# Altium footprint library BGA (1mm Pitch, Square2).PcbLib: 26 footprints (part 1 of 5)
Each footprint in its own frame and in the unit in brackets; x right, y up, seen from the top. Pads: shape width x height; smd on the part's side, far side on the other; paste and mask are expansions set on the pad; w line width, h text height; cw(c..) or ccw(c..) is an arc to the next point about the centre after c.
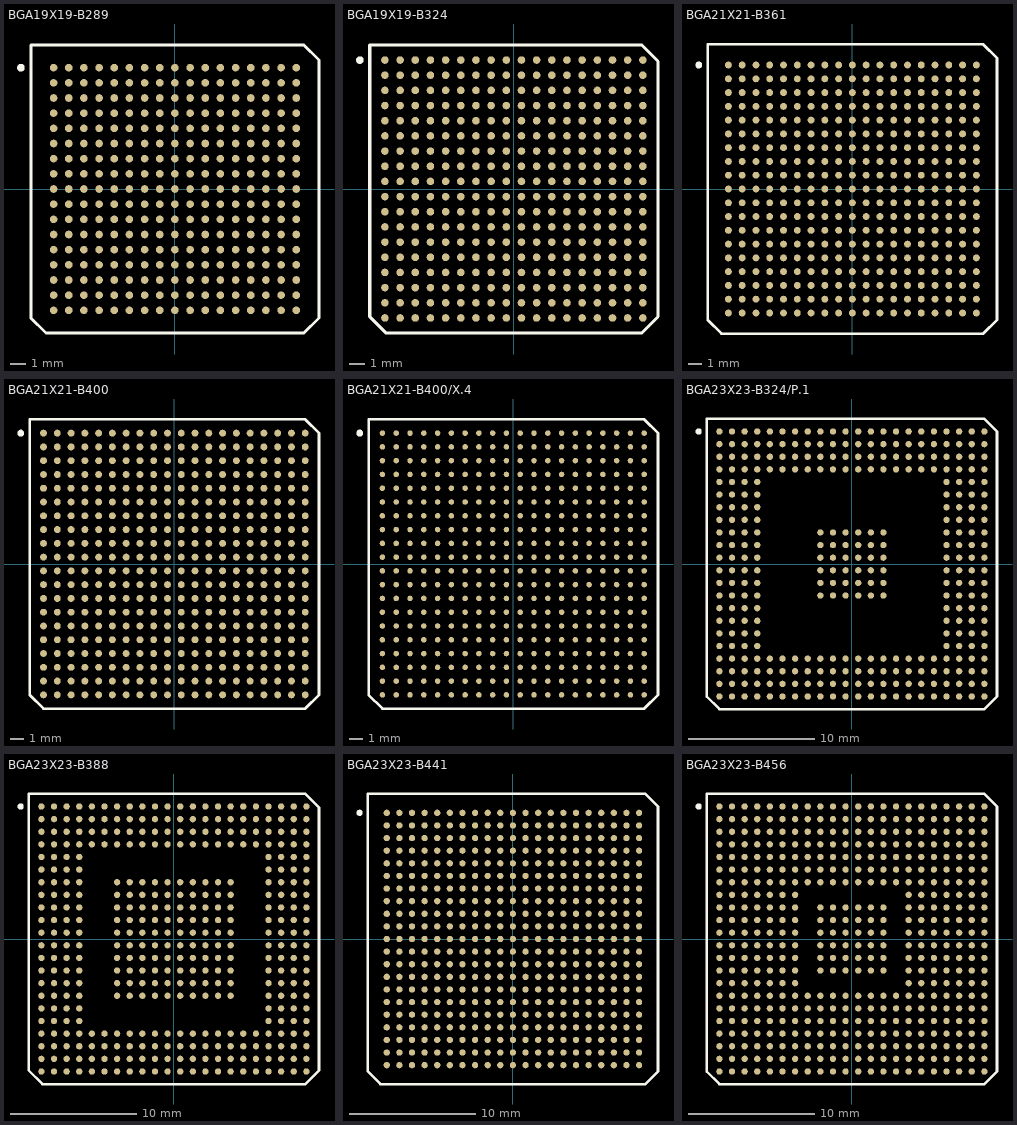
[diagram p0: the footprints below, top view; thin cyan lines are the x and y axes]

## BGA19X19-B289 [mm]
pads (289):
  round 0.5 smd: A1(-8,8) A2(-7,8) A3(-6,8) A4(-5,8) A5(-4,8) A6(-3,8) A7(-2,8) A8(-1,8) A9(0,8) A10(1,8) A11(2,8) A12(3,8) A13(4,8) A14(5,8) A15(6,8) A16(7,8) A17(8,8) B1(-8,7) B2(-7,7) B3(-6,7) B4(-5,7) B5(-4,7) B6(-3,7) B7(-2,7) B8(-1,7) B9(0,7) B10(1,7) B11(2,7) B12(3,7) B13(4,7) B14(5,7) B15(6,7) B16(7,7) B17(8,7) C1(-8,6) C2(-7,6) C3(-6,6) C4(-5,6) C5(-4,6) C6(-3,6) C7(-2,6) C8(-1,6) C9(0,6) C10(1,6) C11(2,6) C12(3,6) C13(4,6) C14(5,6) C15(6,6) C16(7,6) C17(8,6) D1(-8,5) D2(-7,5) D3(-6,5) D4(-5,5) D5(-4,5) D6(-3,5) D7(-2,5) D8(-1,5) D9(0,5) D10(1,5) D11(2,5) D12(3,5) D13(4,5) D14(5,5) D15(6,5) D16(7,5) D17(8,5) E1(-8,4) E2(-7,4) E3(-6,4) E4(-5,4) E5(-4,4) E6(-3,4) E7(-2,4) E8(-1,4) E9(0,4) E10(1,4) E11(2,4) E12(3,4) E13(4,4) E14(5,4) E15(6,4) E16(7,4) E17(8,4) F1(-8,3) F2(-7,3) F3(-6,3) F4(-5,3) F5(-4,3) F6(-3,3) F7(-2,3) F8(-1,3) F9(0,3) F10(1,3) F11(2,3) F12(3,3) F13(4,3) F14(5,3) F15(6,3) F16(7,3) F17(8,3) G1(-8,2) G2(-7,2) G3(-6,2) G4(-5,2) G5(-4,2) G6(-3,2) G7(-2,2) G8(-1,2) G9(0,2) G10(1,2) G11(2,2) G12(3,2) G13(4,2) G14(5,2) G15(6,2) G16(7,2) G17(8,2) H1(-8,1) H2(-7,1) H3(-6,1) H4(-5,1) H5(-4,1) H6(-3,1) H7(-2,1) H8(-1,1) H9(0,1) H10(1,1) H11(2,1) H12(3,1) H13(4,1) H14(5,1) H15(6,1) H16(7,1) H17(8,1) J1(-8,0) J2(-7,0) J3(-6,0) J4(-5,0) J5(-4,0) J6(-3,0) J7(-2,0) J8(-1,0) J9(0,0) J10(1,0) J11(2,0) J12(3,0) J13(4,0) J14(5,0) J15(6,0) J16(7,0) J17(8,0) K1(-8,-1) K2(-7,-1) K3(-6,-1) K4(-5,-1) K5(-4,-1) K6(-3,-1) K7(-2,-1) K8(-1,-1) K9(0,-1) K10(1,-1) K11(2,-1) K12(3,-1) K13(4,-1) K14(5,-1) K15(6,-1) K16(7,-1) K17(8,-1) L1(-8,-2) L2(-7,-2) L3(-6,-2) L4(-5,-2) L5(-4,-2) L6(-3,-2) L7(-2,-2) L8(-1,-2) L9(0,-2) L10(1,-2) L11(2,-2) L12(3,-2) L13(4,-2) L14(5,-2) L15(6,-2) L16(7,-2) L17(8,-2) M1(-8,-3) M2(-7,-3) M3(-6,-3) M4(-5,-3) M5(-4,-3) M6(-3,-3) M7(-2,-3) M8(-1,-3) M9(0,-3) M10(1,-3) M11(2,-3) M12(3,-3) M13(4,-3) M14(5,-3) M15(6,-3) M16(7,-3) M17(8,-3) N1(-8,-4) N2(-7,-4) N3(-6,-4) N4(-5,-4) N5(-4,-4) N6(-3,-4) N7(-2,-4) N8(-1,-4) N9(0,-4) N10(1,-4) N11(2,-4) N12(3,-4) N13(4,-4) N14(5,-4) N15(6,-4) N16(7,-4) N17(8,-4) P1(-8,-5) P2(-7,-5) P3(-6,-5) P4(-5,-5) P5(-4,-5) P6(-3,-5) P7(-2,-5) P8(-1,-5) P9(0,-5) P10(1,-5) P11(2,-5) P12(3,-5) P13(4,-5) P14(5,-5) P15(6,-5) P16(7,-5) P17(8,-5) R1(-8,-6) R2(-7,-6) R3(-6,-6) R4(-5,-6) R5(-4,-6) R6(-3,-6) R7(-2,-6) R8(-1,-6) R9(0,-6) R10(1,-6) R11(2,-6) R12(3,-6) R13(4,-6) R14(5,-6) R15(6,-6) R16(7,-6) R17(8,-6) T1(-8,-7) T2(-7,-7) T3(-6,-7) T4(-5,-7) T5(-4,-7) T6(-3,-7) T7(-2,-7) T8(-1,-7) T9(0,-7) T10(1,-7) T11(2,-7) T12(3,-7) T13(4,-7) T14(5,-7) T15(6,-7) T16(7,-7) T17(8,-7) U1(-8,-8) U2(-7,-8) U3(-6,-8) U4(-5,-8) U5(-4,-8) U6(-3,-8) U7(-2,-8) U8(-1,-8) U9(0,-8) U10(1,-8) U11(2,-8) U12(3,-8) U13(4,-8) U14(5,-8) U15(6,-8) U16(7,-8) U17(8,-8)
Top Overlay:
  circle w0.25: c-10.155,8 r0.125
  lines w0.2: -9.5,-8.5 -9.5,9.5 8.5,9.5 9.5,8.5 9.5,-8.5 8.5,-9.5 -8.5,-9.5 -9.5,-8.5

## BGA19X19-B324 [mm]
pads (324):
  round 0.5 smd: A1(-8.5,8.5) A2(-7.5,8.5) A3(-6.5,8.5) A4(-5.5,8.5) A5(-4.5,8.5) A6(-3.5,8.5) A7(-2.5,8.5) A8(-1.5,8.5) A9(-0.5,8.5) A10(0.5,8.5) A11(1.5,8.5) A12(2.5,8.5) A13(3.5,8.5) A14(4.5,8.5) A15(5.5,8.5) A16(6.5,8.5) A17(7.5,8.5) A18(8.5,8.5) B1(-8.5,7.5) B2(-7.5,7.5) B3(-6.5,7.5) B4(-5.5,7.5) B5(-4.5,7.5) B6(-3.5,7.5) B7(-2.5,7.5) B8(-1.5,7.5) B9(-0.5,7.5) B10(0.5,7.5) B11(1.5,7.5) B12(2.5,7.5) B13(3.5,7.5) B14(4.5,7.5) B15(5.5,7.5) B16(6.5,7.5) B17(7.5,7.5) B18(8.5,7.5) C1(-8.5,6.5) C2(-7.5,6.5) C3(-6.5,6.5) C4(-5.5,6.5) C5(-4.5,6.5) C6(-3.5,6.5) C7(-2.5,6.5) C8(-1.5,6.5) C9(-0.5,6.5) C10(0.5,6.5) C11(1.5,6.5) C12(2.5,6.5) C13(3.5,6.5) C14(4.5,6.5) C15(5.5,6.5) C16(6.5,6.5) C17(7.5,6.5) C18(8.5,6.5) D1(-8.5,5.5) D2(-7.5,5.5) D3(-6.5,5.5) D4(-5.5,5.5) D5(-4.5,5.5) D6(-3.5,5.5) D7(-2.5,5.5) D8(-1.5,5.5) D9(-0.5,5.5) D10(0.5,5.5) D11(1.5,5.5) D12(2.5,5.5) D13(3.5,5.5) D14(4.5,5.5) D15(5.5,5.5) D16(6.5,5.5) D17(7.5,5.5) D18(8.5,5.5) E1(-8.5,4.5) E2(-7.5,4.5) E3(-6.5,4.5) E4(-5.5,4.5) E5(-4.5,4.5) E6(-3.5,4.5) E7(-2.5,4.5) E8(-1.5,4.5) E9(-0.5,4.5) E10(0.5,4.5) E11(1.5,4.5) E12(2.5,4.5) E13(3.5,4.5) E14(4.5,4.5) E15(5.5,4.5) E16(6.5,4.5) E17(7.5,4.5) E18(8.5,4.5) F1(-8.5,3.5) F2(-7.5,3.5) F3(-6.5,3.5) F4(-5.5,3.5) F5(-4.5,3.5) F6(-3.5,3.5) F7(-2.5,3.5) F8(-1.5,3.5) F9(-0.5,3.5) F10(0.5,3.5) F11(1.5,3.5) F12(2.5,3.5) F13(3.5,3.5) F14(4.5,3.5) F15(5.5,3.5) F16(6.5,3.5) F17(7.5,3.5) F18(8.5,3.5) G1(-8.5,2.5) G2(-7.5,2.5) G3(-6.5,2.5) G4(-5.5,2.5) G5(-4.5,2.5) G6(-3.5,2.5) G7(-2.5,2.5) G8(-1.5,2.5) G9(-0.5,2.5) G10(0.5,2.5) G11(1.5,2.5) G12(2.5,2.5) G13(3.5,2.5) G14(4.5,2.5) G15(5.5,2.5) G16(6.5,2.5) G17(7.5,2.5) G18(8.5,2.5) H1(-8.5,1.5) H2(-7.5,1.5) H3(-6.5,1.5) H4(-5.5,1.5) H5(-4.5,1.5) H6(-3.5,1.5) H7(-2.5,1.5) H8(-1.5,1.5) H9(-0.5,1.5) H10(0.5,1.5) H11(1.5,1.5) H12(2.5,1.5) H13(3.5,1.5) H14(4.5,1.5) H15(5.5,1.5) H16(6.5,1.5) H17(7.5,1.5) H18(8.5,1.5) J1(-8.5,0.5) J2(-7.5,0.5) J3(-6.5,0.5) J4(-5.5,0.5) J5(-4.5,0.5) J6(-3.5,0.5) J7(-2.5,0.5) J8(-1.5,0.5) J9(-0.5,0.5) J10(0.5,0.5) J11(1.5,0.5) J12(2.5,0.5) J13(3.5,0.5) J14(4.5,0.5) J15(5.5,0.5) J16(6.5,0.5) J17(7.5,0.5) J18(8.5,0.5) K1(-8.5,-0.5) K2(-7.5,-0.5) K3(-6.5,-0.5) K4(-5.5,-0.5) K5(-4.5,-0.5) K6(-3.5,-0.5) K7(-2.5,-0.5) K8(-1.5,-0.5) K9(-0.5,-0.5) K10(0.5,-0.5) K11(1.5,-0.5) K12(2.5,-0.5) K13(3.5,-0.5) K14(4.5,-0.5) K15(5.5,-0.5) K16(6.5,-0.5) K17(7.5,-0.5) K18(8.5,-0.5) L1(-8.5,-1.5) L2(-7.5,-1.5) L3(-6.5,-1.5) L4(-5.5,-1.5) L5(-4.5,-1.5) L6(-3.5,-1.5) L7(-2.5,-1.5) L8(-1.5,-1.5) L9(-0.5,-1.5) L10(0.5,-1.5) L11(1.5,-1.5) L12(2.5,-1.5) L13(3.5,-1.5) L14(4.5,-1.5) L15(5.5,-1.5) L16(6.5,-1.5) L17(7.5,-1.5) L18(8.5,-1.5) M1(-8.5,-2.5) M2(-7.5,-2.5) M3(-6.5,-2.5) M4(-5.5,-2.5) M5(-4.5,-2.5) M6(-3.5,-2.5) M7(-2.5,-2.5) M8(-1.5,-2.5) M9(-0.5,-2.5) M10(0.5,-2.5) M11(1.5,-2.5) M12(2.5,-2.5) M13(3.5,-2.5) M14(4.5,-2.5) M15(5.5,-2.5) M16(6.5,-2.5) M17(7.5,-2.5) M18(8.5,-2.5) N1(-8.5,-3.5) N2(-7.5,-3.5) N3(-6.5,-3.5) N4(-5.5,-3.5) N5(-4.5,-3.5) N6(-3.5,-3.5) N7(-2.5,-3.5) N8(-1.5,-3.5) N9(-0.5,-3.5) N10(0.5,-3.5) N11(1.5,-3.5) N12(2.5,-3.5) N13(3.5,-3.5) N14(4.5,-3.5) N15(5.5,-3.5) N16(6.5,-3.5) N17(7.5,-3.5) N18(8.5,-3.5) P1(-8.5,-4.5) P2(-7.5,-4.5) P3(-6.5,-4.5) P4(-5.5,-4.5) P5(-4.5,-4.5) P6(-3.5,-4.5) P7(-2.5,-4.5) P8(-1.5,-4.5) P9(-0.5,-4.5) P10(0.5,-4.5) P11(1.5,-4.5) P12(2.5,-4.5) P13(3.5,-4.5) P14(4.5,-4.5) P15(5.5,-4.5) P16(6.5,-4.5) P17(7.5,-4.5) P18(8.5,-4.5) R1(-8.5,-5.5) R2(-7.5,-5.5) R3(-6.5,-5.5) R4(-5.5,-5.5) R5(-4.5,-5.5) R6(-3.5,-5.5) R7(-2.5,-5.5) R8(-1.5,-5.5) R9(-0.5,-5.5) R10(0.5,-5.5) R11(1.5,-5.5) R12(2.5,-5.5) R13(3.5,-5.5) R14(4.5,-5.5) R15(5.5,-5.5) R16(6.5,-5.5) R17(7.5,-5.5) R18(8.5,-5.5) T1(-8.5,-6.5) T2(-7.5,-6.5) T3(-6.5,-6.5) T4(-5.5,-6.5) T5(-4.5,-6.5) T6(-3.5,-6.5) T7(-2.5,-6.5) T8(-1.5,-6.5) T9(-0.5,-6.5) T10(0.5,-6.5) T11(1.5,-6.5) T12(2.5,-6.5) T13(3.5,-6.5) T14(4.5,-6.5) T15(5.5,-6.5) T16(6.5,-6.5) T17(7.5,-6.5) T18(8.5,-6.5) U1(-8.5,-7.5) U2(-7.5,-7.5) U3(-6.5,-7.5) U4(-5.5,-7.5) U5(-4.5,-7.5) U6(-3.5,-7.5) U7(-2.5,-7.5) U8(-1.5,-7.5) U9(-0.5,-7.5) U10(0.5,-7.5) U11(1.5,-7.5) U12(2.5,-7.5) U13(3.5,-7.5) U14(4.5,-7.5) U15(5.5,-7.5) U16(6.5,-7.5) U17(7.5,-7.5) U18(8.5,-7.5) V1(-8.5,-8.5) V2(-7.5,-8.5) V3(-6.5,-8.5) V4(-5.5,-8.5) V5(-4.5,-8.5) V6(-3.5,-8.5) V7(-2.5,-8.5) V8(-1.5,-8.5) V9(-0.5,-8.5) V10(0.5,-8.5) V11(1.5,-8.5) V12(2.5,-8.5) V13(3.5,-8.5) V14(4.5,-8.5) V15(5.5,-8.5) V16(6.5,-8.5) V17(7.5,-8.5) V18(8.5,-8.5)
Top Overlay:
  circle w0.25: c-10.15,8.5 r0.125
  lines w0.2: -9.5,-8.419 -9.5,9.5 8.419,9.5 9.5,8.419 9.5,-8.419 8.419,-9.5 -8.419,-9.5 -9.5,-8.419

## BGA21X21-B361 [mm]
pads (361):
  round 0.5 smd: A1(-9,9) A2(-8,9) A3(-7,9) A4(-6,9) A5(-5,9) A6(-4,9) A7(-3,9) A8(-2,9) A9(-1,9) A10(0,9) A11(1,9) A12(2,9) A13(3,9) A14(4,9) A15(5,9) A16(6,9) A17(7,9) A18(8,9) A19(9,9) B1(-9,8) B2(-8,8) B3(-7,8) B4(-6,8) B5(-5,8) B6(-4,8) B7(-3,8) B8(-2,8) B9(-1,8) B10(0,8) B11(1,8) B12(2,8) B13(3,8) B14(4,8) B15(5,8) B16(6,8) B17(7,8) B18(8,8) B19(9,8) C1(-9,7) C2(-8,7) C3(-7,7) C4(-6,7) C5(-5,7) C6(-4,7) C7(-3,7) C8(-2,7) C9(-1,7) C10(0,7) C11(1,7) C12(2,7) C13(3,7) C14(4,7) C15(5,7) C16(6,7) C17(7,7) C18(8,7) C19(9,7) D1(-9,6) D2(-8,6) D3(-7,6) D4(-6,6) D5(-5,6) D6(-4,6) D7(-3,6) D8(-2,6) D9(-1,6) D10(0,6) D11(1,6) D12(2,6) D13(3,6) D14(4,6) D15(5,6) D16(6,6) D17(7,6) D18(8,6) D19(9,6) E1(-9,5) E2(-8,5) E3(-7,5) E4(-6,5) E5(-5,5) E6(-4,5) E7(-3,5) E8(-2,5) E9(-1,5) E10(0,5) E11(1,5) E12(2,5) E13(3,5) E14(4,5) E15(5,5) E16(6,5) E17(7,5) E18(8,5) E19(9,5) F1(-9,4) F2(-8,4) F3(-7,4) F4(-6,4) F5(-5,4) F6(-4,4) F7(-3,4) F8(-2,4) F9(-1,4) F10(0,4) F11(1,4) F12(2,4) F13(3,4) F14(4,4) F15(5,4) F16(6,4) F17(7,4) F18(8,4) F19(9,4) G1(-9,3) G2(-8,3) G3(-7,3) G4(-6,3) G5(-5,3) G6(-4,3) G7(-3,3) G8(-2,3) G9(-1,3) G10(0,3) G11(1,3) G12(2,3) G13(3,3) G14(4,3) G15(5,3) G16(6,3) G17(7,3) G18(8,3) G19(9,3) H1(-9,2) H2(-8,2) H3(-7,2) H4(-6,2) H5(-5,2) H6(-4,2) H7(-3,2) H8(-2,2) H9(-1,2) H10(0,2) H11(1,2) H12(2,2) H13(3,2) H14(4,2) H15(5,2) H16(6,2) H17(7,2) H18(8,2) H19(9,2) J1(-9,1) J2(-8,1) J3(-7,1) J4(-6,1) J5(-5,1) J6(-4,1) J7(-3,1) J8(-2,1) J9(-1,1) J10(0,1) J11(1,1) J12(2,1) J13(3,1) J14(4,1) J15(5,1) J16(6,1) J17(7,1) J18(8,1) J19(9,1) K1(-9,0) K2(-8,0) K3(-7,0) K4(-6,0) K5(-5,0) K6(-4,0) K7(-3,0) K8(-2,0) K9(-1,0) K10(0,0) K11(1,0) K12(2,0) K13(3,0) K14(4,0) K15(5,0) K16(6,0) K17(7,0) K18(8,0) K19(9,0) L1(-9,-1) L2(-8,-1) L3(-7,-1) L4(-6,-1) L5(-5,-1) L6(-4,-1) L7(-3,-1) L8(-2,-1) L9(-1,-1) L10(0,-1) L11(1,-1) L12(2,-1) L13(3,-1) L14(4,-1) L15(5,-1) L16(6,-1) L17(7,-1) L18(8,-1) L19(9,-1) M1(-9,-2) M2(-8,-2) M3(-7,-2) M4(-6,-2) M5(-5,-2) M6(-4,-2) M7(-3,-2) M8(-2,-2) M9(-1,-2) M10(0,-2) M11(1,-2) M12(2,-2) M13(3,-2) M14(4,-2) M15(5,-2) M16(6,-2) M17(7,-2) M18(8,-2) M19(9,-2) N1(-9,-3) N2(-8,-3) N3(-7,-3) N4(-6,-3) N5(-5,-3) N6(-4,-3) N7(-3,-3) N8(-2,-3) N9(-1,-3) N10(0,-3) N11(1,-3) N12(2,-3) N13(3,-3) N14(4,-3) N15(5,-3) N16(6,-3) N17(7,-3) N18(8,-3) N19(9,-3) P1(-9,-4) P2(-8,-4) P3(-7,-4) P4(-6,-4) P5(-5,-4) P6(-4,-4) P7(-3,-4) P8(-2,-4) P9(-1,-4) P10(0,-4) P11(1,-4) P12(2,-4) P13(3,-4) P14(4,-4) P15(5,-4) P16(6,-4) P17(7,-4) P18(8,-4) P19(9,-4) R1(-9,-5) R2(-8,-5) R3(-7,-5) R4(-6,-5) R5(-5,-5) R6(-4,-5) R7(-3,-5) R8(-2,-5) R9(-1,-5) R10(0,-5) R11(1,-5) R12(2,-5) R13(3,-5) R14(4,-5) R15(5,-5) R16(6,-5) R17(7,-5) R18(8,-5) R19(9,-5) T1(-9,-6) T2(-8,-6) T3(-7,-6) T4(-6,-6) T5(-5,-6) T6(-4,-6) T7(-3,-6) T8(-2,-6) T9(-1,-6) T10(0,-6) T11(1,-6) T12(2,-6) T13(3,-6) T14(4,-6) T15(5,-6) T16(6,-6) T17(7,-6) T18(8,-6) T19(9,-6) U1(-9,-7) U2(-8,-7) U3(-7,-7) U4(-6,-7) U5(-5,-7) U6(-4,-7) U7(-3,-7) U8(-2,-7) U9(-1,-7) U10(0,-7) U11(1,-7) U12(2,-7) U13(3,-7) U14(4,-7) U15(5,-7) U16(6,-7) U17(7,-7) U18(8,-7) U19(9,-7) V1(-9,-8) V2(-8,-8) V3(-7,-8) V4(-6,-8) V5(-5,-8) V6(-4,-8) V7(-3,-8) V8(-2,-8) V9(-1,-8) V10(0,-8) V11(1,-8) V12(2,-8) V13(3,-8) V14(4,-8) V15(5,-8) V16(6,-8) V17(7,-8) V18(8,-8) V19(9,-8) W1(-9,-9) W2(-8,-9) W3(-7,-9) W4(-6,-9) W5(-5,-9) W6(-4,-9) W7(-3,-9) W8(-2,-9) W9(-1,-9) W10(0,-9) W11(1,-9) W12(2,-9) W13(3,-9) W14(4,-9) W15(5,-9) W16(6,-9) W17(7,-9) W18(8,-9) W19(9,-9)
Top Overlay:
  circle w0.25: c-11.155,9 r0.125
  lines w0.2: -10.5,-9.5 -10.5,10.5 9.5,10.5 10.5,9.5 10.5,-9.5 9.5,-10.5 -9.5,-10.5 -10.5,-9.5

## BGA21X21-B400 [mm]
pads (400):
  round 0.5 smd: A1(-9.5,9.5) A2(-8.5,9.5) A3(-7.5,9.5) A4(-6.5,9.5) A5(-5.5,9.5) A6(-4.5,9.5) A7(-3.5,9.5) A8(-2.5,9.5) A9(-1.5,9.5) A10(-0.5,9.5) A11(0.5,9.5) A12(1.5,9.5) A13(2.5,9.5) A14(3.5,9.5) A15(4.5,9.5) A16(5.5,9.5) A17(6.5,9.5) A18(7.5,9.5) A19(8.5,9.5) A20(9.5,9.5) B1(-9.5,8.5) B2(-8.5,8.5) B3(-7.5,8.5) B4(-6.5,8.5) B5(-5.5,8.5) B6(-4.5,8.5) B7(-3.5,8.5) B8(-2.5,8.5) B9(-1.5,8.5) B10(-0.5,8.5) B11(0.5,8.5) B12(1.5,8.5) B13(2.5,8.5) B14(3.5,8.5) B15(4.5,8.5) B16(5.5,8.5) B17(6.5,8.5) B18(7.5,8.5) B19(8.5,8.5) B20(9.5,8.5) C1(-9.5,7.5) C2(-8.5,7.5) C3(-7.5,7.5) C4(-6.5,7.5) C5(-5.5,7.5) C6(-4.5,7.5) C7(-3.5,7.5) C8(-2.5,7.5) C9(-1.5,7.5) C10(-0.5,7.5) C11(0.5,7.5) C12(1.5,7.5) C13(2.5,7.5) C14(3.5,7.5) C15(4.5,7.5) C16(5.5,7.5) C17(6.5,7.5) C18(7.5,7.5) C19(8.5,7.5) C20(9.5,7.5) D1(-9.5,6.5) D2(-8.5,6.5) D3(-7.5,6.5) D4(-6.5,6.5) D5(-5.5,6.5) D6(-4.5,6.5) D7(-3.5,6.5) D8(-2.5,6.5) D9(-1.5,6.5) D10(-0.5,6.5) D11(0.5,6.5) D12(1.5,6.5) D13(2.5,6.5) D14(3.5,6.5) D15(4.5,6.5) D16(5.5,6.5) D17(6.5,6.5) D18(7.5,6.5) D19(8.5,6.5) D20(9.5,6.5) E1(-9.5,5.5) E2(-8.5,5.5) E3(-7.5,5.5) E4(-6.5,5.5) E5(-5.5,5.5) E6(-4.5,5.5) E7(-3.5,5.5) E8(-2.5,5.5) E9(-1.5,5.5) E10(-0.5,5.5) E11(0.5,5.5) E12(1.5,5.5) E13(2.5,5.5) E14(3.5,5.5) E15(4.5,5.5) E16(5.5,5.5) E17(6.5,5.5) E18(7.5,5.5) E19(8.5,5.5) E20(9.5,5.5) F1(-9.5,4.5) F2(-8.5,4.5) F3(-7.5,4.5) F4(-6.5,4.5) F5(-5.5,4.5) F6(-4.5,4.5) F7(-3.5,4.5) F8(-2.5,4.5) F9(-1.5,4.5) F10(-0.5,4.5) F11(0.5,4.5) F12(1.5,4.5) F13(2.5,4.5) F14(3.5,4.5) F15(4.5,4.5) F16(5.5,4.5) F17(6.5,4.5) F18(7.5,4.5) F19(8.5,4.5) F20(9.5,4.5) G1(-9.5,3.5) G2(-8.5,3.5) G3(-7.5,3.5) G4(-6.5,3.5) G5(-5.5,3.5) G6(-4.5,3.5) G7(-3.5,3.5) G8(-2.5,3.5) G9(-1.5,3.5) G10(-0.5,3.5) G11(0.5,3.5) G12(1.5,3.5) G13(2.5,3.5) G14(3.5,3.5) G15(4.5,3.5) G16(5.5,3.5) G17(6.5,3.5) G18(7.5,3.5) G19(8.5,3.5) G20(9.5,3.5) H1(-9.5,2.5) H2(-8.5,2.5) H3(-7.5,2.5) H4(-6.5,2.5) H5(-5.5,2.5) H6(-4.5,2.5) H7(-3.5,2.5) H8(-2.5,2.5) H9(-1.5,2.5) H10(-0.5,2.5) H11(0.5,2.5) H12(1.5,2.5) H13(2.5,2.5) H14(3.5,2.5) H15(4.5,2.5) H16(5.5,2.5) H17(6.5,2.5) H18(7.5,2.5) H19(8.5,2.5) H20(9.5,2.5) J1(-9.5,1.5) J2(-8.5,1.5) J3(-7.5,1.5) J4(-6.5,1.5) J5(-5.5,1.5) J6(-4.5,1.5) J7(-3.5,1.5) J8(-2.5,1.5) J9(-1.5,1.5) J10(-0.5,1.5) J11(0.5,1.5) J12(1.5,1.5) J13(2.5,1.5) J14(3.5,1.5) J15(4.5,1.5) J16(5.5,1.5) J17(6.5,1.5) J18(7.5,1.5) J19(8.5,1.5) J20(9.5,1.5) K1(-9.5,0.5) K2(-8.5,0.5) K3(-7.5,0.5) K4(-6.5,0.5) K5(-5.5,0.5) K6(-4.5,0.5) K7(-3.5,0.5) K8(-2.5,0.5) K9(-1.5,0.5) K10(-0.5,0.5) K11(0.5,0.5) K12(1.5,0.5) K13(2.5,0.5) K14(3.5,0.5) K15(4.5,0.5) K16(5.5,0.5) K17(6.5,0.5) K18(7.5,0.5) K19(8.5,0.5) K20(9.5,0.5) L1(-9.5,-0.5) L2(-8.5,-0.5) L3(-7.5,-0.5) L4(-6.5,-0.5) L5(-5.5,-0.5) L6(-4.5,-0.5) L7(-3.5,-0.5) L8(-2.5,-0.5) L9(-1.5,-0.5) L10(-0.5,-0.5) L11(0.5,-0.5) L12(1.5,-0.5) L13(2.5,-0.5) L14(3.5,-0.5) L15(4.5,-0.5) L16(5.5,-0.5) L17(6.5,-0.5) L18(7.5,-0.5) L19(8.5,-0.5) L20(9.5,-0.5) M1(-9.5,-1.5) M2(-8.5,-1.5) M3(-7.5,-1.5) M4(-6.5,-1.5) M5(-5.5,-1.5) M6(-4.5,-1.5) M7(-3.5,-1.5) M8(-2.5,-1.5) M9(-1.5,-1.5) M10(-0.5,-1.5) M11(0.5,-1.5) M12(1.5,-1.5) M13(2.5,-1.5) M14(3.5,-1.5) M15(4.5,-1.5) M16(5.5,-1.5) M17(6.5,-1.5) M18(7.5,-1.5) M19(8.5,-1.5) M20(9.5,-1.5) N1(-9.5,-2.5) N2(-8.5,-2.5) N3(-7.5,-2.5) N4(-6.5,-2.5) N5(-5.5,-2.5) N6(-4.5,-2.5) N7(-3.5,-2.5) N8(-2.5,-2.5) N9(-1.5,-2.5) N10(-0.5,-2.5) N11(0.5,-2.5) N12(1.5,-2.5) N13(2.5,-2.5) N14(3.5,-2.5) N15(4.5,-2.5) N16(5.5,-2.5) N17(6.5,-2.5) N18(7.5,-2.5) N19(8.5,-2.5) N20(9.5,-2.5) P1(-9.5,-3.5) P2(-8.5,-3.5) P3(-7.5,-3.5) P4(-6.5,-3.5) P5(-5.5,-3.5) P6(-4.5,-3.5) P7(-3.5,-3.5) P8(-2.5,-3.5) P9(-1.5,-3.5) P10(-0.5,-3.5) P11(0.5,-3.5) P12(1.5,-3.5) P13(2.5,-3.5) P14(3.5,-3.5) P15(4.5,-3.5) P16(5.5,-3.5) P17(6.5,-3.5) P18(7.5,-3.5) P19(8.5,-3.5) P20(9.5,-3.5) R1(-9.5,-4.5) R2(-8.5,-4.5) R3(-7.5,-4.5) R4(-6.5,-4.5) R5(-5.5,-4.5) R6(-4.5,-4.5) R7(-3.5,-4.5) R8(-2.5,-4.5) R9(-1.5,-4.5) R10(-0.5,-4.5) R11(0.5,-4.5) R12(1.5,-4.5) R13(2.5,-4.5) R14(3.5,-4.5) R15(4.5,-4.5) R16(5.5,-4.5) R17(6.5,-4.5) R18(7.5,-4.5) R19(8.5,-4.5) R20(9.5,-4.5) T1(-9.5,-5.5) T2(-8.5,-5.5) T3(-7.5,-5.5) T4(-6.5,-5.5) T5(-5.5,-5.5) T6(-4.5,-5.5) T7(-3.5,-5.5) T8(-2.5,-5.5) T9(-1.5,-5.5) T10(-0.5,-5.5) T11(0.5,-5.5) T12(1.5,-5.5) T13(2.5,-5.5) T14(3.5,-5.5) T15(4.5,-5.5) T16(5.5,-5.5) T17(6.5,-5.5) T18(7.5,-5.5) T19(8.5,-5.5) T20(9.5,-5.5) U1(-9.5,-6.5) U2(-8.5,-6.5) U3(-7.5,-6.5) U4(-6.5,-6.5) U5(-5.5,-6.5) U6(-4.5,-6.5) U7(-3.5,-6.5) U8(-2.5,-6.5) U9(-1.5,-6.5) U10(-0.5,-6.5) U11(0.5,-6.5) U12(1.5,-6.5) U13(2.5,-6.5) U14(3.5,-6.5) U15(4.5,-6.5) U16(5.5,-6.5) U17(6.5,-6.5) U18(7.5,-6.5) U19(8.5,-6.5) U20(9.5,-6.5) V1(-9.5,-7.5) V2(-8.5,-7.5) V3(-7.5,-7.5) V4(-6.5,-7.5) V5(-5.5,-7.5) V6(-4.5,-7.5) V7(-3.5,-7.5) V8(-2.5,-7.5) V9(-1.5,-7.5) V10(-0.5,-7.5) V11(0.5,-7.5) V12(1.5,-7.5) V13(2.5,-7.5) V14(3.5,-7.5) V15(4.5,-7.5) V16(5.5,-7.5) V17(6.5,-7.5) V18(7.5,-7.5) V19(8.5,-7.5) V20(9.5,-7.5) W1(-9.5,-8.5) W2(-8.5,-8.5) W3(-7.5,-8.5) W4(-6.5,-8.5) W5(-5.5,-8.5) W6(-4.5,-8.5) W7(-3.5,-8.5) W8(-2.5,-8.5) W9(-1.5,-8.5) W10(-0.5,-8.5) W11(0.5,-8.5) W12(1.5,-8.5) W13(2.5,-8.5) W14(3.5,-8.5) W15(4.5,-8.5) W16(5.5,-8.5) W17(6.5,-8.5) W18(7.5,-8.5) W19(8.5,-8.5) W20(9.5,-8.5) Y1(-9.5,-9.5) Y2(-8.5,-9.5) Y3(-7.5,-9.5) Y4(-6.5,-9.5) Y5(-5.5,-9.5) Y6(-4.5,-9.5) Y7(-3.5,-9.5) Y8(-2.5,-9.5) Y9(-1.5,-9.5) Y10(-0.5,-9.5) Y11(0.5,-9.5) Y12(1.5,-9.5) Y13(2.5,-9.5) Y14(3.5,-9.5) Y15(4.5,-9.5) Y16(5.5,-9.5) Y17(6.5,-9.5) Y18(7.5,-9.5) Y19(8.5,-9.5) Y20(9.5,-9.5)
Top Overlay:
  circle w0.25: c-11.155,9.5 r0.125
  lines w0.2: -10.5,-9.5 -10.5,10.5 9.5,10.5 10.5,9.5 10.5,-9.5 9.5,-10.5 -9.5,-10.5 -10.5,-9.5

## BGA21X21-B400/X.4 [mm]
pads (400):
  round 0.4 smd: A1(-9.5,9.5) A2(-8.5,9.5) A3(-7.5,9.5) A4(-6.5,9.5) A5(-5.5,9.5) A6(-4.5,9.5) A7(-3.5,9.5) A8(-2.5,9.5) A9(-1.5,9.5) A10(-0.5,9.5) A11(0.5,9.5) A12(1.5,9.5) A13(2.5,9.5) A14(3.5,9.5) A15(4.5,9.5) A16(5.5,9.5) A17(6.5,9.5) A18(7.5,9.5) A19(8.5,9.5) A20(9.5,9.5) B1(-9.5,8.5) B2(-8.5,8.5) B3(-7.5,8.5) B4(-6.5,8.5) B5(-5.5,8.5) B6(-4.5,8.5) B7(-3.5,8.5) B8(-2.5,8.5) B9(-1.5,8.5) B10(-0.5,8.5) B11(0.5,8.5) B12(1.5,8.5) B13(2.5,8.5) B14(3.5,8.5) B15(4.5,8.5) B16(5.5,8.5) B17(6.5,8.5) B18(7.5,8.5) B19(8.5,8.5) B20(9.5,8.5) C1(-9.5,7.5) C2(-8.5,7.5) C3(-7.5,7.5) C4(-6.5,7.5) C5(-5.5,7.5) C6(-4.5,7.5) C7(-3.5,7.5) C8(-2.5,7.5) C9(-1.5,7.5) C10(-0.5,7.5) C11(0.5,7.5) C12(1.5,7.5) C13(2.5,7.5) C14(3.5,7.5) C15(4.5,7.5) C16(5.5,7.5) C17(6.5,7.5) C18(7.5,7.5) C19(8.5,7.5) C20(9.5,7.5) D1(-9.5,6.5) D2(-8.5,6.5) D3(-7.5,6.5) D4(-6.5,6.5) D5(-5.5,6.5) D6(-4.5,6.5) D7(-3.5,6.5) D8(-2.5,6.5) D9(-1.5,6.5) D10(-0.5,6.5) D11(0.5,6.5) D12(1.5,6.5) D13(2.5,6.5) D14(3.5,6.5) D15(4.5,6.5) D16(5.5,6.5) D17(6.5,6.5) D18(7.5,6.5) D19(8.5,6.5) D20(9.5,6.5) E1(-9.5,5.5) E2(-8.5,5.5) E3(-7.5,5.5) E4(-6.5,5.5) E5(-5.5,5.5) E6(-4.5,5.5) E7(-3.5,5.5) E8(-2.5,5.5) E9(-1.5,5.5) E10(-0.5,5.5) E11(0.5,5.5) E12(1.5,5.5) E13(2.5,5.5) E14(3.5,5.5) E15(4.5,5.5) E16(5.5,5.5) E17(6.5,5.5) E18(7.5,5.5) E19(8.5,5.5) E20(9.5,5.5) F1(-9.5,4.5) F2(-8.5,4.5) F3(-7.5,4.5) F4(-6.5,4.5) F5(-5.5,4.5) F6(-4.5,4.5) F7(-3.5,4.5) F8(-2.5,4.5) F9(-1.5,4.5) F10(-0.5,4.5) F11(0.5,4.5) F12(1.5,4.5) F13(2.5,4.5) F14(3.5,4.5) F15(4.5,4.5) F16(5.5,4.5) F17(6.5,4.5) F18(7.5,4.5) F19(8.5,4.5) F20(9.5,4.5) G1(-9.5,3.5) G2(-8.5,3.5) G3(-7.5,3.5) G4(-6.5,3.5) G5(-5.5,3.5) G6(-4.5,3.5) G7(-3.5,3.5) G8(-2.5,3.5) G9(-1.5,3.5) G10(-0.5,3.5) G11(0.5,3.5) G12(1.5,3.5) G13(2.5,3.5) G14(3.5,3.5) G15(4.5,3.5) G16(5.5,3.5) G17(6.5,3.5) G18(7.5,3.5) G19(8.5,3.5) G20(9.5,3.5) H1(-9.5,2.5) H2(-8.5,2.5) H3(-7.5,2.5) H4(-6.5,2.5) H5(-5.5,2.5) H6(-4.5,2.5) H7(-3.5,2.5) H8(-2.5,2.5) H9(-1.5,2.5) H10(-0.5,2.5) H11(0.5,2.5) H12(1.5,2.5) H13(2.5,2.5) H14(3.5,2.5) H15(4.5,2.5) H16(5.5,2.5) H17(6.5,2.5) H18(7.5,2.5) H19(8.5,2.5) H20(9.5,2.5) J1(-9.5,1.5) J2(-8.5,1.5) J3(-7.5,1.5) J4(-6.5,1.5) J5(-5.5,1.5) J6(-4.5,1.5) J7(-3.5,1.5) J8(-2.5,1.5) J9(-1.5,1.5) J10(-0.5,1.5) J11(0.5,1.5) J12(1.5,1.5) J13(2.5,1.5) J14(3.5,1.5) J15(4.5,1.5) J16(5.5,1.5) J17(6.5,1.5) J18(7.5,1.5) J19(8.5,1.5) J20(9.5,1.5) K1(-9.5,0.5) K2(-8.5,0.5) K3(-7.5,0.5) K4(-6.5,0.5) K5(-5.5,0.5) K6(-4.5,0.5) K7(-3.5,0.5) K8(-2.5,0.5) K9(-1.5,0.5) K10(-0.5,0.5) K11(0.5,0.5) K12(1.5,0.5) K13(2.5,0.5) K14(3.5,0.5) K15(4.5,0.5) K16(5.5,0.5) K17(6.5,0.5) K18(7.5,0.5) K19(8.5,0.5) K20(9.5,0.5) L1(-9.5,-0.5) L2(-8.5,-0.5) L3(-7.5,-0.5) L4(-6.5,-0.5) L5(-5.5,-0.5) L6(-4.5,-0.5) L7(-3.5,-0.5) L8(-2.5,-0.5) L9(-1.5,-0.5) L10(-0.5,-0.5) L11(0.5,-0.5) L12(1.5,-0.5) L13(2.5,-0.5) L14(3.5,-0.5) L15(4.5,-0.5) L16(5.5,-0.5) L17(6.5,-0.5) L18(7.5,-0.5) L19(8.5,-0.5) L20(9.5,-0.5) M1(-9.5,-1.5) M2(-8.5,-1.5) M3(-7.5,-1.5) M4(-6.5,-1.5) M5(-5.5,-1.5) M6(-4.5,-1.5) M7(-3.5,-1.5) M8(-2.5,-1.5) M9(-1.5,-1.5) M10(-0.5,-1.5) M11(0.5,-1.5) M12(1.5,-1.5) M13(2.5,-1.5) M14(3.5,-1.5) M15(4.5,-1.5) M16(5.5,-1.5) M17(6.5,-1.5) M18(7.5,-1.5) M19(8.5,-1.5) M20(9.5,-1.5) N1(-9.5,-2.5) N2(-8.5,-2.5) N3(-7.5,-2.5) N4(-6.5,-2.5) N5(-5.5,-2.5) N6(-4.5,-2.5) N7(-3.5,-2.5) N8(-2.5,-2.5) N9(-1.5,-2.5) N10(-0.5,-2.5) N11(0.5,-2.5) N12(1.5,-2.5) N13(2.5,-2.5) N14(3.5,-2.5) N15(4.5,-2.5) N16(5.5,-2.5) N17(6.5,-2.5) N18(7.5,-2.5) N19(8.5,-2.5) N20(9.5,-2.5) P1(-9.5,-3.5) P2(-8.5,-3.5) P3(-7.5,-3.5) P4(-6.5,-3.5) P5(-5.5,-3.5) P6(-4.5,-3.5) P7(-3.5,-3.5) P8(-2.5,-3.5) P9(-1.5,-3.5) P10(-0.5,-3.5) P11(0.5,-3.5) P12(1.5,-3.5) P13(2.5,-3.5) P14(3.5,-3.5) P15(4.5,-3.5) P16(5.5,-3.5) P17(6.5,-3.5) P18(7.5,-3.5) P19(8.5,-3.5) P20(9.5,-3.5) R1(-9.5,-4.5) R2(-8.5,-4.5) R3(-7.5,-4.5) R4(-6.5,-4.5) R5(-5.5,-4.5) R6(-4.5,-4.5) R7(-3.5,-4.5) R8(-2.5,-4.5) R9(-1.5,-4.5) R10(-0.5,-4.5) R11(0.5,-4.5) R12(1.5,-4.5) R13(2.5,-4.5) R14(3.5,-4.5) R15(4.5,-4.5) R16(5.5,-4.5) R17(6.5,-4.5) R18(7.5,-4.5) R19(8.5,-4.5) R20(9.5,-4.5) T1(-9.5,-5.5) T2(-8.5,-5.5) T3(-7.5,-5.5) T4(-6.5,-5.5) T5(-5.5,-5.5) T6(-4.5,-5.5) T7(-3.5,-5.5) T8(-2.5,-5.5) T9(-1.5,-5.5) T10(-0.5,-5.5) T11(0.5,-5.5) T12(1.5,-5.5) T13(2.5,-5.5) T14(3.5,-5.5) T15(4.5,-5.5) T16(5.5,-5.5) T17(6.5,-5.5) T18(7.5,-5.5) T19(8.5,-5.5) T20(9.5,-5.5) U1(-9.5,-6.5) U2(-8.5,-6.5) U3(-7.5,-6.5) U4(-6.5,-6.5) U5(-5.5,-6.5) U6(-4.5,-6.5) U7(-3.5,-6.5) U8(-2.5,-6.5) U9(-1.5,-6.5) U10(-0.5,-6.5) U11(0.5,-6.5) U12(1.5,-6.5) U13(2.5,-6.5) U14(3.5,-6.5) U15(4.5,-6.5) U16(5.5,-6.5) U17(6.5,-6.5) U18(7.5,-6.5) U19(8.5,-6.5) U20(9.5,-6.5) V1(-9.5,-7.5) V2(-8.5,-7.5) V3(-7.5,-7.5) V4(-6.5,-7.5) V5(-5.5,-7.5) V6(-4.5,-7.5) V7(-3.5,-7.5) V8(-2.5,-7.5) V9(-1.5,-7.5) V10(-0.5,-7.5) V11(0.5,-7.5) V12(1.5,-7.5) V13(2.5,-7.5) V14(3.5,-7.5) V15(4.5,-7.5) V16(5.5,-7.5) V17(6.5,-7.5) V18(7.5,-7.5) V19(8.5,-7.5) V20(9.5,-7.5) W1(-9.5,-8.5) W2(-8.5,-8.5) W3(-7.5,-8.5) W4(-6.5,-8.5) W5(-5.5,-8.5) W6(-4.5,-8.5) W7(-3.5,-8.5) W8(-2.5,-8.5) W9(-1.5,-8.5) W10(-0.5,-8.5) W11(0.5,-8.5) W12(1.5,-8.5) W13(2.5,-8.5) W14(3.5,-8.5) W15(4.5,-8.5) W16(5.5,-8.5) W17(6.5,-8.5) W18(7.5,-8.5) W19(8.5,-8.5) W20(9.5,-8.5) Y1(-9.5,-9.5) Y2(-8.5,-9.5) Y3(-7.5,-9.5) Y4(-6.5,-9.5) Y5(-5.5,-9.5) Y6(-4.5,-9.5) Y7(-3.5,-9.5) Y8(-2.5,-9.5) Y9(-1.5,-9.5) Y10(-0.5,-9.5) Y11(0.5,-9.5) Y12(1.5,-9.5) Y13(2.5,-9.5) Y14(3.5,-9.5) Y15(4.5,-9.5) Y16(5.5,-9.5) Y17(6.5,-9.5) Y18(7.5,-9.5) Y19(8.5,-9.5) Y20(9.5,-9.5)
Top Overlay:
  circle w0.25: c-11.15,9.5 r0.125
  lines w0.2: -10.5,-9.5 -10.5,10.5 9.5,10.5 10.5,9.5 10.5,-9.5 9.5,-10.5 -9.5,-10.5 -10.5,-9.5

## BGA23X23-B324/P.1 [mm]
pads (324):
  round 0.5 smd: A1(-10.5,10.5) A2(-9.5,10.5) A3(-8.5,10.5) A4(-7.5,10.5) A5(-6.5,10.5) A6(-5.5,10.5) A7(-4.5,10.5) A8(-3.5,10.5) A9(-2.5,10.5) A10(-1.5,10.5) A11(-0.5,10.5) A12(0.5,10.5) A13(1.5,10.5) A14(2.5,10.5) A15(3.5,10.5) A16(4.5,10.5) A17(5.5,10.5) A18(6.5,10.5) A19(7.5,10.5) A20(8.5,10.5) A21(9.5,10.5) A22(10.5,10.5) AA1(-10.5,-9.5) AA2(-9.5,-9.5) AA3(-8.5,-9.5) AA4(-7.5,-9.5) AA5(-6.5,-9.5) AA6(-5.5,-9.5) AA7(-4.5,-9.5) AA8(-3.5,-9.5) AA9(-2.5,-9.5) AA10(-1.5,-9.5) AA11(-0.5,-9.5) AA12(0.5,-9.5) AA13(1.5,-9.5) AA14(2.5,-9.5) AA15(3.5,-9.5) AA16(4.5,-9.5) AA17(5.5,-9.5) AA18(6.5,-9.5) AA19(7.5,-9.5) AA20(8.5,-9.5) AA21(9.5,-9.5) AA22(10.5,-9.5) AB1(-10.5,-10.5) AB2(-9.5,-10.5) AB3(-8.5,-10.5) AB4(-7.5,-10.5) AB5(-6.5,-10.5) AB6(-5.5,-10.5) AB7(-4.5,-10.5) AB8(-3.5,-10.5) AB9(-2.5,-10.5) AB10(-1.5,-10.5) AB11(-0.5,-10.5) AB12(0.5,-10.5) AB13(1.5,-10.5) AB14(2.5,-10.5) AB15(3.5,-10.5) AB16(4.5,-10.5) AB17(5.5,-10.5) AB18(6.5,-10.5) AB19(7.5,-10.5) AB20(8.5,-10.5) AB21(9.5,-10.5) AB22(10.5,-10.5) B1(-10.5,9.5) B2(-9.5,9.5) B3(-8.5,9.5) B4(-7.5,9.5) B5(-6.5,9.5) B6(-5.5,9.5) B7(-4.5,9.5) B8(-3.5,9.5) B9(-2.5,9.5) B10(-1.5,9.5) B11(-0.5,9.5) B12(0.5,9.5) B13(1.5,9.5) B14(2.5,9.5) B15(3.5,9.5) B16(4.5,9.5) B17(5.5,9.5) B18(6.5,9.5) B19(7.5,9.5) B20(8.5,9.5) B21(9.5,9.5) B22(10.5,9.5) C1(-10.5,8.5) C2(-9.5,8.5) C3(-8.5,8.5) C4(-7.5,8.5) C5(-6.5,8.5) C6(-5.5,8.5) C7(-4.5,8.5) C8(-3.5,8.5) C9(-2.5,8.5) C10(-1.5,8.5) C11(-0.5,8.5) C12(0.5,8.5) C13(1.5,8.5) C14(2.5,8.5) C15(3.5,8.5) C16(4.5,8.5) C17(5.5,8.5) C18(6.5,8.5) C19(7.5,8.5) C20(8.5,8.5) C21(9.5,8.5) C22(10.5,8.5) D1(-10.5,7.5) D2(-9.5,7.5) D3(-8.5,7.5) D4(-7.5,7.5) D5(-6.5,7.5) D6(-5.5,7.5) D7(-4.5,7.5) D8(-3.5,7.5) D9(-2.5,7.5) D10(-1.5,7.5) D11(-0.5,7.5) D12(0.5,7.5) D13(1.5,7.5) D14(2.5,7.5) D15(3.5,7.5) D16(4.5,7.5) D17(5.5,7.5) D18(6.5,7.5) D19(7.5,7.5) D20(8.5,7.5) D21(9.5,7.5) D22(10.5,7.5) E1(-10.5,6.5) E2(-9.5,6.5) E3(-8.5,6.5) E4(-7.5,6.5) E19(7.5,6.5) E20(8.5,6.5) E21(9.5,6.5) E22(10.5,6.5) F1(-10.5,5.5) F2(-9.5,5.5) F3(-8.5,5.5) F4(-7.5,5.5) F19(7.5,5.5) F20(8.5,5.5) F21(9.5,5.5) F22(10.5,5.5) G1(-10.5,4.5) G2(-9.5,4.5) G3(-8.5,4.5) G4(-7.5,4.5) G19(7.5,4.5) G20(8.5,4.5) G21(9.5,4.5) G22(10.5,4.5) H1(-10.5,3.5) H2(-9.5,3.5) H3(-8.5,3.5) H4(-7.5,3.5) H19(7.5,3.5) H20(8.5,3.5) H21(9.5,3.5) H22(10.5,3.5) J1(-10.5,2.5) J2(-9.5,2.5) J3(-8.5,2.5) J4(-7.5,2.5) J9(-2.5,2.5) J10(-1.5,2.5) J11(-0.5,2.5) J12(0.5,2.5) J13(1.5,2.5) J14(2.5,2.5) J19(7.5,2.5) J20(8.5,2.5) J21(9.5,2.5) J22(10.5,2.5) K1(-10.5,1.5) K2(-9.5,1.5) K3(-8.5,1.5) K4(-7.5,1.5) K9(-2.5,1.5) K10(-1.5,1.5) K11(-0.5,1.5) K12(0.5,1.5) K13(1.5,1.5) K14(2.5,1.5) K19(7.5,1.5) K20(8.5,1.5) K21(9.5,1.5) K22(10.5,1.5) L1(-10.5,0.5) L2(-9.5,0.5) L3(-8.5,0.5) L4(-7.5,0.5) L9(-2.5,0.5) L10(-1.5,0.5) L11(-0.5,0.5) L12(0.5,0.5) L13(1.5,0.5) L14(2.5,0.5) L19(7.5,0.5) L20(8.5,0.5) L21(9.5,0.5) L22(10.5,0.5) M1(-10.5,-0.5) M2(-9.5,-0.5) M3(-8.5,-0.5) M4(-7.5,-0.5) M9(-2.5,-0.5) M10(-1.5,-0.5) M11(-0.5,-0.5) M12(0.5,-0.5) M13(1.5,-0.5) M14(2.5,-0.5) M19(7.5,-0.5) M20(8.5,-0.5) M21(9.5,-0.5) M22(10.5,-0.5) N1(-10.5,-1.5) N2(-9.5,-1.5) N3(-8.5,-1.5) N4(-7.5,-1.5) N9(-2.5,-1.5) N10(-1.5,-1.5) N11(-0.5,-1.5) N12(0.5,-1.5) N13(1.5,-1.5) N14(2.5,-1.5) N19(7.5,-1.5) N20(8.5,-1.5) N21(9.5,-1.5) N22(10.5,-1.5) P1(-10.5,-2.5) P2(-9.5,-2.5) P3(-8.5,-2.5) P4(-7.5,-2.5) P9(-2.5,-2.5) P10(-1.5,-2.5) P11(-0.5,-2.5) P12(0.5,-2.5) P13(1.5,-2.5) P14(2.5,-2.5) P19(7.5,-2.5) P20(8.5,-2.5) P21(9.5,-2.5) P22(10.5,-2.5) R1(-10.5,-3.5) R2(-9.5,-3.5) R3(-8.5,-3.5) R4(-7.5,-3.5) R19(7.5,-3.5) R20(8.5,-3.5) R21(9.5,-3.5) R22(10.5,-3.5) T1(-10.5,-4.5) T2(-9.5,-4.5) T3(-8.5,-4.5) T4(-7.5,-4.5) T19(7.5,-4.5) T20(8.5,-4.5) T21(9.5,-4.5) T22(10.5,-4.5) U1(-10.5,-5.5) U2(-9.5,-5.5) U3(-8.5,-5.5) U4(-7.5,-5.5) U19(7.5,-5.5) U20(8.5,-5.5) U21(9.5,-5.5) U22(10.5,-5.5) V1(-10.5,-6.5) V2(-9.5,-6.5) V3(-8.5,-6.5) V4(-7.5,-6.5) V19(7.5,-6.5) V20(8.5,-6.5) V21(9.5,-6.5) V22(10.5,-6.5) W1(-10.5,-7.5) W2(-9.5,-7.5) W3(-8.5,-7.5) W4(-7.5,-7.5) W5(-6.5,-7.5) W6(-5.5,-7.5) W7(-4.5,-7.5) W8(-3.5,-7.5) W9(-2.5,-7.5) W10(-1.5,-7.5) W11(-0.5,-7.5) W12(0.5,-7.5) W13(1.5,-7.5) W14(2.5,-7.5) W15(3.5,-7.5) W16(4.5,-7.5) W17(5.5,-7.5) W18(6.5,-7.5) W19(7.5,-7.5) W20(8.5,-7.5) W21(9.5,-7.5) W22(10.5,-7.5) Y1(-10.5,-8.5) Y2(-9.5,-8.5) Y3(-8.5,-8.5) Y4(-7.5,-8.5) Y5(-6.5,-8.5) Y6(-5.5,-8.5) Y7(-4.5,-8.5) Y8(-3.5,-8.5) Y9(-2.5,-8.5) Y10(-1.5,-8.5) Y11(-0.5,-8.5) Y12(0.5,-8.5) Y13(1.5,-8.5) Y14(2.5,-8.5) Y15(3.5,-8.5) Y16(4.5,-8.5) Y17(5.5,-8.5) Y18(6.5,-8.5) Y19(7.5,-8.5) Y20(8.5,-8.5) Y21(9.5,-8.5) Y22(10.5,-8.5)
Top Overlay:
  circle w0.25: c-12.15,10.5 r0.125
  lines w0.2: 10.5,-11.5 11.5,-10.5 11.5,10.5 ; 10.5,-11.5 10.5,-11.5 ; 10.5,-11.5 -10.5,-11.5 -11.5,-10.5 -11.5,11.5 10.5,11.5 11.5,10.5 ; 11.5,10.5 11.5,10.5

## BGA23X23-B388 [mm]
pads (388):
  round 0.5 smd: A1(-10.5,10.5) A2(-9.5,10.5) A3(-8.5,10.5) A4(-7.5,10.5) A5(-6.5,10.5) A6(-5.5,10.5) A7(-4.5,10.5) A8(-3.5,10.5) A9(-2.5,10.5) A10(-1.5,10.5) A11(-0.5,10.5) A12(0.5,10.5) A13(1.5,10.5) A14(2.5,10.5) A15(3.5,10.5) A16(4.5,10.5) A17(5.5,10.5) A18(6.5,10.5) A19(7.5,10.5) A20(8.5,10.5) A21(9.5,10.5) A22(10.5,10.5) AA1(-10.5,-9.5) AA2(-9.5,-9.5) AA3(-8.5,-9.5) AA4(-7.5,-9.5) AA5(-6.5,-9.5) AA6(-5.5,-9.5) AA7(-4.5,-9.5) AA8(-3.5,-9.5) AA9(-2.5,-9.5) AA10(-1.5,-9.5) AA11(-0.5,-9.5) AA12(0.5,-9.5) AA13(1.5,-9.5) AA14(2.5,-9.5) AA15(3.5,-9.5) AA16(4.5,-9.5) AA17(5.5,-9.5) AA18(6.5,-9.5) AA19(7.5,-9.5) AA20(8.5,-9.5) AA21(9.5,-9.5) AA22(10.5,-9.5) AB1(-10.5,-10.5) AB2(-9.5,-10.5) AB3(-8.5,-10.5) AB4(-7.5,-10.5) AB5(-6.5,-10.5) AB6(-5.5,-10.5) AB7(-4.5,-10.5) AB8(-3.5,-10.5) AB9(-2.5,-10.5) AB10(-1.5,-10.5) AB11(-0.5,-10.5) AB12(0.5,-10.5) AB13(1.5,-10.5) AB14(2.5,-10.5) AB15(3.5,-10.5) AB16(4.5,-10.5) AB17(5.5,-10.5) AB18(6.5,-10.5) AB19(7.5,-10.5) AB20(8.5,-10.5) AB21(9.5,-10.5) AB22(10.5,-10.5) B1(-10.5,9.5) B2(-9.5,9.5) B3(-8.5,9.5) B4(-7.5,9.5) B5(-6.5,9.5) B6(-5.5,9.5) B7(-4.5,9.5) B8(-3.5,9.5) B9(-2.5,9.5) B10(-1.5,9.5) B11(-0.5,9.5) B12(0.5,9.5) B13(1.5,9.5) B14(2.5,9.5) B15(3.5,9.5) B16(4.5,9.5) B17(5.5,9.5) B18(6.5,9.5) B19(7.5,9.5) B20(8.5,9.5) B21(9.5,9.5) B22(10.5,9.5) C1(-10.5,8.5) C2(-9.5,8.5) C3(-8.5,8.5) C4(-7.5,8.5) C5(-6.5,8.5) C6(-5.5,8.5) C7(-4.5,8.5) C8(-3.5,8.5) C9(-2.5,8.5) C10(-1.5,8.5) C11(-0.5,8.5) C12(0.5,8.5) C13(1.5,8.5) C14(2.5,8.5) C15(3.5,8.5) C16(4.5,8.5) C17(5.5,8.5) C18(6.5,8.5) C19(7.5,8.5) C20(8.5,8.5) C21(9.5,8.5) C22(10.5,8.5) D1(-10.5,7.5) D2(-9.5,7.5) D3(-8.5,7.5) D4(-7.5,7.5) D5(-6.5,7.5) D6(-5.5,7.5) D7(-4.5,7.5) D8(-3.5,7.5) D9(-2.5,7.5) D10(-1.5,7.5) D11(-0.5,7.5) D12(0.5,7.5) D13(1.5,7.5) D14(2.5,7.5) D15(3.5,7.5) D16(4.5,7.5) D17(5.5,7.5) D18(6.5,7.5) D19(7.5,7.5) D20(8.5,7.5) D21(9.5,7.5) D22(10.5,7.5) E1(-10.5,6.5) E2(-9.5,6.5) E3(-8.5,6.5) E4(-7.5,6.5) E19(7.5,6.5) E20(8.5,6.5) E21(9.5,6.5) E22(10.5,6.5) F1(-10.5,5.5) F2(-9.5,5.5) F3(-8.5,5.5) F4(-7.5,5.5) F19(7.5,5.5) F20(8.5,5.5) F21(9.5,5.5) F22(10.5,5.5) G1(-10.5,4.5) G2(-9.5,4.5) G3(-8.5,4.5) G4(-7.5,4.5) G7(-4.5,4.5) G8(-3.5,4.5) G9(-2.5,4.5) G10(-1.5,4.5) G11(-0.5,4.5) G12(0.5,4.5) G13(1.5,4.5) G14(2.5,4.5) G15(3.5,4.5) G16(4.5,4.5) G19(7.5,4.5) G20(8.5,4.5) G21(9.5,4.5) G22(10.5,4.5) H1(-10.5,3.5) H2(-9.5,3.5) H3(-8.5,3.5) H4(-7.5,3.5) H7(-4.5,3.5) H8(-3.5,3.5) H9(-2.5,3.5) H10(-1.5,3.5) H11(-0.5,3.5) H12(0.5,3.5) H13(1.5,3.5) H14(2.5,3.5) H15(3.5,3.5) H16(4.5,3.5) H19(7.5,3.5) H20(8.5,3.5) H21(9.5,3.5) H22(10.5,3.5) J1(-10.5,2.5) J2(-9.5,2.5) J3(-8.5,2.5) J4(-7.5,2.5) J7(-4.5,2.5) J8(-3.5,2.5) J9(-2.5,2.5) J10(-1.5,2.5) J11(-0.5,2.5) J12(0.5,2.5) J13(1.5,2.5) J14(2.5,2.5) J15(3.5,2.5) J16(4.5,2.5) J19(7.5,2.5) J20(8.5,2.5) J21(9.5,2.5) J22(10.5,2.5) K1(-10.5,1.5) K2(-9.5,1.5) K3(-8.5,1.5) K4(-7.5,1.5) K7(-4.5,1.5) K8(-3.5,1.5) K9(-2.5,1.5) K10(-1.5,1.5) K11(-0.5,1.5) K12(0.5,1.5) K13(1.5,1.5) K14(2.5,1.5) K15(3.5,1.5) K16(4.5,1.5) K19(7.5,1.5) K20(8.5,1.5) K21(9.5,1.5) K22(10.5,1.5) L1(-10.5,0.5) L2(-9.5,0.5) L3(-8.5,0.5) L4(-7.5,0.5) L7(-4.5,0.5) L8(-3.5,0.5) L9(-2.5,0.5) L10(-1.5,0.5) L11(-0.5,0.5) L12(0.5,0.5) L13(1.5,0.5) L14(2.5,0.5) L15(3.5,0.5) L16(4.5,0.5) L19(7.5,0.5) L20(8.5,0.5) L21(9.5,0.5) L22(10.5,0.5) M1(-10.5,-0.5) M2(-9.5,-0.5) M3(-8.5,-0.5) M4(-7.5,-0.5) M7(-4.5,-0.5) M8(-3.5,-0.5) M9(-2.5,-0.5) M10(-1.5,-0.5) M11(-0.5,-0.5) M12(0.5,-0.5) M13(1.5,-0.5) M14(2.5,-0.5) M15(3.5,-0.5) M16(4.5,-0.5) M19(7.5,-0.5) M20(8.5,-0.5) M21(9.5,-0.5) M22(10.5,-0.5) N1(-10.5,-1.5) N2(-9.5,-1.5) N3(-8.5,-1.5) N4(-7.5,-1.5) N7(-4.5,-1.5) N8(-3.5,-1.5) N9(-2.5,-1.5) N10(-1.5,-1.5) N11(-0.5,-1.5) N12(0.5,-1.5) N13(1.5,-1.5) N14(2.5,-1.5) N15(3.5,-1.5) N16(4.5,-1.5) N19(7.5,-1.5) N20(8.5,-1.5) N21(9.5,-1.5) N22(10.5,-1.5) P1(-10.5,-2.5) P2(-9.5,-2.5) P3(-8.5,-2.5) P4(-7.5,-2.5) P7(-4.5,-2.5) P8(-3.5,-2.5) P9(-2.5,-2.5) P10(-1.5,-2.5) P11(-0.5,-2.5) P12(0.5,-2.5) P13(1.5,-2.5) P14(2.5,-2.5) P15(3.5,-2.5) P16(4.5,-2.5) P19(7.5,-2.5) P20(8.5,-2.5) P21(9.5,-2.5) P22(10.5,-2.5) R1(-10.5,-3.5) R2(-9.5,-3.5) R3(-8.5,-3.5) R4(-7.5,-3.5) R7(-4.5,-3.5) R8(-3.5,-3.5) R9(-2.5,-3.5) R10(-1.5,-3.5) R11(-0.5,-3.5) R12(0.5,-3.5) R13(1.5,-3.5) R14(2.5,-3.5) R15(3.5,-3.5) R16(4.5,-3.5) R19(7.5,-3.5) R20(8.5,-3.5) R21(9.5,-3.5) R22(10.5,-3.5) T1(-10.5,-4.5) T2(-9.5,-4.5) T3(-8.5,-4.5) T4(-7.5,-4.5) T7(-4.5,-4.5) T8(-3.5,-4.5) T9(-2.5,-4.5) T10(-1.5,-4.5) T11(-0.5,-4.5) T12(0.5,-4.5) T13(1.5,-4.5) T14(2.5,-4.5) T15(3.5,-4.5) T16(4.5,-4.5) T19(7.5,-4.5) T20(8.5,-4.5) T21(9.5,-4.5) T22(10.5,-4.5) U1(-10.5,-5.5) U2(-9.5,-5.5) U3(-8.5,-5.5) U4(-7.5,-5.5) U19(7.5,-5.5) U20(8.5,-5.5) U21(9.5,-5.5) U22(10.5,-5.5) V1(-10.5,-6.5) V2(-9.5,-6.5) V3(-8.5,-6.5) V4(-7.5,-6.5) V19(7.5,-6.5) V20(8.5,-6.5) V21(9.5,-6.5) V22(10.5,-6.5) W1(-10.5,-7.5) W2(-9.5,-7.5) W3(-8.5,-7.5) W4(-7.5,-7.5) W5(-6.5,-7.5) W6(-5.5,-7.5) W7(-4.5,-7.5) W8(-3.5,-7.5) W9(-2.5,-7.5) W10(-1.5,-7.5) W11(-0.5,-7.5) W12(0.5,-7.5) W13(1.5,-7.5) W14(2.5,-7.5) W15(3.5,-7.5) W16(4.5,-7.5) W17(5.5,-7.5) W18(6.5,-7.5) W19(7.5,-7.5) W20(8.5,-7.5) W21(9.5,-7.5) W22(10.5,-7.5) Y1(-10.5,-8.5) Y2(-9.5,-8.5) Y3(-8.5,-8.5) Y4(-7.5,-8.5) Y5(-6.5,-8.5) Y6(-5.5,-8.5) Y7(-4.5,-8.5) Y8(-3.5,-8.5) Y9(-2.5,-8.5) Y10(-1.5,-8.5) Y11(-0.5,-8.5) Y12(0.5,-8.5) Y13(1.5,-8.5) Y14(2.5,-8.5) Y15(3.5,-8.5) Y16(4.5,-8.5) Y17(5.5,-8.5) Y18(6.5,-8.5) Y19(7.5,-8.5) Y20(8.5,-8.5) Y21(9.5,-8.5) Y22(10.5,-8.5)
Top Overlay:
  circle w0.25: c-12.15,10.5 r0.125
  lines w0.2: -11.5,-10.419 -11.5,11.5 10.419,11.5 11.5,10.419 11.5,-10.419 10.419,-11.5 -10.419,-11.5 -11.5,-10.419

## BGA23X23-B441 [mm]
pads (441):
  round 0.5 smd: A1(-10,10) A2(-9,10) A3(-8,10) A4(-7,10) A5(-6,10) A6(-5,10) A7(-4,10) A8(-3,10) A9(-2,10) A10(-1,10) A11(0,10) A12(1,10) A13(2,10) A14(3,10) A15(4,10) A16(5,10) A17(6,10) A18(7,10) A19(8,10) A20(9,10) A21(10,10) AA1(-10,-10) AA2(-9,-10) AA3(-8,-10) AA4(-7,-10) AA5(-6,-10) AA6(-5,-10) AA7(-4,-10) AA8(-3,-10) AA9(-2,-10) AA10(-1,-10) AA11(0,-10) AA12(1,-10) AA13(2,-10) AA14(3,-10) AA15(4,-10) AA16(5,-10) AA17(6,-10) AA18(7,-10) AA19(8,-10) AA20(9,-10) AA21(10,-10) B1(-10,9) B2(-9,9) B3(-8,9) B4(-7,9) B5(-6,9) B6(-5,9) B7(-4,9) B8(-3,9) B9(-2,9) B10(-1,9) B11(0,9) B12(1,9) B13(2,9) B14(3,9) B15(4,9) B16(5,9) B17(6,9) B18(7,9) B19(8,9) B20(9,9) B21(10,9) C1(-10,8) C2(-9,8) C3(-8,8) C4(-7,8) C5(-6,8) C6(-5,8) C7(-4,8) C8(-3,8) C9(-2,8) C10(-1,8) C11(0,8) C12(1,8) C13(2,8) C14(3,8) C15(4,8) C16(5,8) C17(6,8) C18(7,8) C19(8,8) C20(9,8) C21(10,8) D1(-10,7) D2(-9,7) D3(-8,7) D4(-7,7) D5(-6,7) D6(-5,7) D7(-4,7) D8(-3,7) D9(-2,7) D10(-1,7) D11(0,7) D12(1,7) D13(2,7) D14(3,7) D15(4,7) D16(5,7) D17(6,7) D18(7,7) D19(8,7) D20(9,7) D21(10,7) E1(-10,6) E2(-9,6) E3(-8,6) E4(-7,6) E5(-6,6) E6(-5,6) E7(-4,6) E8(-3,6) E9(-2,6) E10(-1,6) E11(0,6) E12(1,6) E13(2,6) E14(3,6) E15(4,6) E16(5,6) E17(6,6) E18(7,6) E19(8,6) E20(9,6) E21(10,6) F1(-10,5) F2(-9,5) F3(-8,5) F4(-7,5) F5(-6,5) F6(-5,5) F7(-4,5) F8(-3,5) F9(-2,5) F10(-1,5) F11(0,5) F12(1,5) F13(2,5) F14(3,5) F15(4,5) F16(5,5) F17(6,5) F18(7,5) F19(8,5) F20(9,5) F21(10,5) G1(-10,4) G2(-9,4) G3(-8,4) G4(-7,4) G5(-6,4) G6(-5,4) G7(-4,4) G8(-3,4) G9(-2,4) G10(-1,4) G11(0,4) G12(1,4) G13(2,4) G14(3,4) G15(4,4) G16(5,4) G17(6,4) G18(7,4) G19(8,4) G20(9,4) G21(10,4) H1(-10,3) H2(-9,3) H3(-8,3) H4(-7,3) H5(-6,3) H6(-5,3) H7(-4,3) H8(-3,3) H9(-2,3) H10(-1,3) H11(0,3) H12(1,3) H13(2,3) H14(3,3) H15(4,3) H16(5,3) H17(6,3) H18(7,3) H19(8,3) H20(9,3) H21(10,3) J1(-10,2) J2(-9,2) J3(-8,2) J4(-7,2) J5(-6,2) J6(-5,2) J7(-4,2) J8(-3,2) J9(-2,2) J10(-1,2) J11(0,2) J12(1,2) J13(2,2) J14(3,2) J15(4,2) J16(5,2) J17(6,2) J18(7,2) J19(8,2) J20(9,2) J21(10,2) K1(-10,1) K2(-9,1) K3(-8,1) K4(-7,1) K5(-6,1) K6(-5,1) K7(-4,1) K8(-3,1) K9(-2,1) K10(-1,1) K11(0,1) K12(1,1) K13(2,1) K14(3,1) K15(4,1) K16(5,1) K17(6,1) K18(7,1) K19(8,1) K20(9,1) K21(10,1) L1(-10,0) L2(-9,0) L3(-8,0) L4(-7,0) L5(-6,0) L6(-5,0) L7(-4,0) L8(-3,0) L9(-2,0) L10(-1,0) L11(0,0) L12(1,0) L13(2,0) L14(3,0) L15(4,0) L16(5,0) L17(6,0) L18(7,0) L19(8,0) L20(9,0) L21(10,0) M1(-10,-1) M2(-9,-1) M3(-8,-1) M4(-7,-1) M5(-6,-1) M6(-5,-1) M7(-4,-1) M8(-3,-1) M9(-2,-1) M10(-1,-1) M11(0,-1) M12(1,-1) M13(2,-1) M14(3,-1) M15(4,-1) M16(5,-1) M17(6,-1) M18(7,-1) M19(8,-1) M20(9,-1) M21(10,-1) N1(-10,-2) N2(-9,-2) N3(-8,-2) N4(-7,-2) N5(-6,-2) N6(-5,-2) N7(-4,-2) N8(-3,-2) N9(-2,-2) N10(-1,-2) N11(0,-2) N12(1,-2) N13(2,-2) N14(3,-2) N15(4,-2) N16(5,-2) N17(6,-2) N18(7,-2) N19(8,-2) N20(9,-2) N21(10,-2) P1(-10,-3) P2(-9,-3) P3(-8,-3) P4(-7,-3) P5(-6,-3) P6(-5,-3) P7(-4,-3) P8(-3,-3) P9(-2,-3) P10(-1,-3) P11(0,-3) P12(1,-3) P13(2,-3) P14(3,-3) P15(4,-3) P16(5,-3) P17(6,-3) P18(7,-3) P19(8,-3) P20(9,-3) P21(10,-3) R1(-10,-4) R2(-9,-4) R3(-8,-4) R4(-7,-4) R5(-6,-4) R6(-5,-4) R7(-4,-4) R8(-3,-4) R9(-2,-4) R10(-1,-4) R11(0,-4) R12(1,-4) R13(2,-4) R14(3,-4) R15(4,-4) R16(5,-4) R17(6,-4) R18(7,-4) R19(8,-4) R20(9,-4) R21(10,-4) T1(-10,-5) T2(-9,-5) T3(-8,-5) T4(-7,-5) T5(-6,-5) T6(-5,-5) T7(-4,-5) T8(-3,-5) T9(-2,-5) T10(-1,-5) T11(0,-5) T12(1,-5) T13(2,-5) T14(3,-5) T15(4,-5) T16(5,-5) T17(6,-5) T18(7,-5) T19(8,-5) T20(9,-5) T21(10,-5) U1(-10,-6) U2(-9,-6) U3(-8,-6) U4(-7,-6) U5(-6,-6) U6(-5,-6) U7(-4,-6) U8(-3,-6) U9(-2,-6) U10(-1,-6) U11(0,-6) U12(1,-6) U13(2,-6) U14(3,-6) U15(4,-6) U16(5,-6) U17(6,-6) U18(7,-6) U19(8,-6) U20(9,-6) U21(10,-6) V1(-10,-7) V2(-9,-7) V3(-8,-7) V4(-7,-7) V5(-6,-7) V6(-5,-7) V7(-4,-7) V8(-3,-7) V9(-2,-7) V10(-1,-7) V11(0,-7) V12(1,-7) V13(2,-7) V14(3,-7) V15(4,-7) V16(5,-7) V17(6,-7) V18(7,-7) V19(8,-7) V20(9,-7) V21(10,-7) W1(-10,-8) W2(-9,-8) W3(-8,-8) W4(-7,-8) W5(-6,-8) W6(-5,-8) W7(-4,-8) W8(-3,-8) W9(-2,-8) W10(-1,-8) W11(0,-8) W12(1,-8) W13(2,-8) W14(3,-8) W15(4,-8) W16(5,-8) W17(6,-8) W18(7,-8) W19(8,-8) W20(9,-8) W21(10,-8) Y1(-10,-9) Y2(-9,-9) Y3(-8,-9) Y4(-7,-9) Y5(-6,-9) Y6(-5,-9) Y7(-4,-9) Y8(-3,-9) Y9(-2,-9) Y10(-1,-9) Y11(0,-9) Y12(1,-9) Y13(2,-9) Y14(3,-9) Y15(4,-9) Y16(5,-9) Y17(6,-9) Y18(7,-9) Y19(8,-9) Y20(9,-9) Y21(10,-9)
Top Overlay:
  circle w0.25: c-12.155,10 r0.125
  lines w0.2: -11.5,-10.5 -11.5,11.5 10.5,11.5 11.5,10.5 11.5,-10.5 10.5,-11.5 -10.5,-11.5 -11.5,-10.5

## BGA23X23-B456 [mm]
pads (456):
  round 0.5 smd: A1(-10.5,10.5) A2(-9.5,10.5) A3(-8.5,10.5) A4(-7.5,10.5) A5(-6.5,10.5) A6(-5.5,10.5) A7(-4.5,10.5) A8(-3.5,10.5) A9(-2.5,10.5) A10(-1.5,10.5) A11(-0.5,10.5) A12(0.5,10.5) A13(1.5,10.5) A14(2.5,10.5) A15(3.5,10.5) A16(4.5,10.5) A17(5.5,10.5) A18(6.5,10.5) A19(7.5,10.5) A20(8.5,10.5) A21(9.5,10.5) A22(10.5,10.5) AA1(-10.5,-9.5) AA2(-9.5,-9.5) AA3(-8.5,-9.5) AA4(-7.5,-9.5) AA5(-6.5,-9.5) AA6(-5.5,-9.5) AA7(-4.5,-9.5) AA8(-3.5,-9.5) AA9(-2.5,-9.5) AA10(-1.5,-9.5) AA11(-0.5,-9.5) AA12(0.5,-9.5) AA13(1.5,-9.5) AA14(2.5,-9.5) AA15(3.5,-9.5) AA16(4.5,-9.5) AA17(5.5,-9.5) AA18(6.5,-9.5) AA19(7.5,-9.5) AA20(8.5,-9.5) AA21(9.5,-9.5) AA22(10.5,-9.5) AB1(-10.5,-10.5) AB2(-9.5,-10.5) AB3(-8.5,-10.5) AB4(-7.5,-10.5) AB5(-6.5,-10.5) AB6(-5.5,-10.5) AB7(-4.5,-10.5) AB8(-3.5,-10.5) AB9(-2.5,-10.5) AB10(-1.5,-10.5) AB11(-0.5,-10.5) AB12(0.5,-10.5) AB13(1.5,-10.5) AB14(2.5,-10.5) AB15(3.5,-10.5) AB16(4.5,-10.5) AB17(5.5,-10.5) AB18(6.5,-10.5) AB19(7.5,-10.5) AB20(8.5,-10.5) AB21(9.5,-10.5) AB22(10.5,-10.5) B1(-10.5,9.5) B2(-9.5,9.5) B3(-8.5,9.5) B4(-7.5,9.5) B5(-6.5,9.5) B6(-5.5,9.5) B7(-4.5,9.5) B8(-3.5,9.5) B9(-2.5,9.5) B10(-1.5,9.5) B11(-0.5,9.5) B12(0.5,9.5) B13(1.5,9.5) B14(2.5,9.5) B15(3.5,9.5) B16(4.5,9.5) B17(5.5,9.5) B18(6.5,9.5) B19(7.5,9.5) B20(8.5,9.5) B21(9.5,9.5) B22(10.5,9.5) C1(-10.5,8.5) C2(-9.5,8.5) C3(-8.5,8.5) C4(-7.5,8.5) C5(-6.5,8.5) C6(-5.5,8.5) C7(-4.5,8.5) C8(-3.5,8.5) C9(-2.5,8.5) C10(-1.5,8.5) C11(-0.5,8.5) C12(0.5,8.5) C13(1.5,8.5) C14(2.5,8.5) C15(3.5,8.5) C16(4.5,8.5) C17(5.5,8.5) C18(6.5,8.5) C19(7.5,8.5) C20(8.5,8.5) C21(9.5,8.5) C22(10.5,8.5) D1(-10.5,7.5) D2(-9.5,7.5) D3(-8.5,7.5) D4(-7.5,7.5) D5(-6.5,7.5) D6(-5.5,7.5) D7(-4.5,7.5) D8(-3.5,7.5) D9(-2.5,7.5) D10(-1.5,7.5) D11(-0.5,7.5) D12(0.5,7.5) D13(1.5,7.5) D14(2.5,7.5) D15(3.5,7.5) D16(4.5,7.5) D17(5.5,7.5) D18(6.5,7.5) D19(7.5,7.5) D20(8.5,7.5) D21(9.5,7.5) D22(10.5,7.5) E1(-10.5,6.5) E2(-9.5,6.5) E3(-8.5,6.5) E4(-7.5,6.5) E5(-6.5,6.5) E6(-5.5,6.5) E7(-4.5,6.5) E8(-3.5,6.5) E9(-2.5,6.5) E10(-1.5,6.5) E11(-0.5,6.5) E12(0.5,6.5) E13(1.5,6.5) E14(2.5,6.5) E15(3.5,6.5) E16(4.5,6.5) E17(5.5,6.5) E18(6.5,6.5) E19(7.5,6.5) E20(8.5,6.5) E21(9.5,6.5) E22(10.5,6.5) F1(-10.5,5.5) F2(-9.5,5.5) F3(-8.5,5.5) F4(-7.5,5.5) F5(-6.5,5.5) F6(-5.5,5.5) F7(-4.5,5.5) F8(-3.5,5.5) F9(-2.5,5.5) F10(-1.5,5.5) F11(-0.5,5.5) F12(0.5,5.5) F13(1.5,5.5) F14(2.5,5.5) F15(3.5,5.5) F16(4.5,5.5) F17(5.5,5.5) F18(6.5,5.5) F19(7.5,5.5) F20(8.5,5.5) F21(9.5,5.5) F22(10.5,5.5) G1(-10.5,4.5) G2(-9.5,4.5) G3(-8.5,4.5) G4(-7.5,4.5) G5(-6.5,4.5) G6(-5.5,4.5) G7(-4.5,4.5) G8(-3.5,4.5) G9(-2.5,4.5) G10(-1.5,4.5) G11(-0.5,4.5) G12(0.5,4.5) G13(1.5,4.5) G14(2.5,4.5) G15(3.5,4.5) G16(4.5,4.5) G17(5.5,4.5) G18(6.5,4.5) G19(7.5,4.5) G20(8.5,4.5) G21(9.5,4.5) G22(10.5,4.5) H1(-10.5,3.5) H2(-9.5,3.5) H3(-8.5,3.5) H4(-7.5,3.5) H5(-6.5,3.5) H6(-5.5,3.5) H7(-4.5,3.5) H16(4.5,3.5) H17(5.5,3.5) H18(6.5,3.5) H19(7.5,3.5) H20(8.5,3.5) H21(9.5,3.5) H22(10.5,3.5) J1(-10.5,2.5) J2(-9.5,2.5) J3(-8.5,2.5) J4(-7.5,2.5) J5(-6.5,2.5) J6(-5.5,2.5) J7(-4.5,2.5) J9(-2.5,2.5) J10(-1.5,2.5) J11(-0.5,2.5) J12(0.5,2.5) J13(1.5,2.5) J14(2.5,2.5) J16(4.5,2.5) J17(5.5,2.5) J18(6.5,2.5) J19(7.5,2.5) J20(8.5,2.5) J21(9.5,2.5) J22(10.5,2.5) K1(-10.5,1.5) K2(-9.5,1.5) K3(-8.5,1.5) K4(-7.5,1.5) K5(-6.5,1.5) K6(-5.5,1.5) K7(-4.5,1.5) K9(-2.5,1.5) K10(-1.5,1.5) K11(-0.5,1.5) K12(0.5,1.5) K13(1.5,1.5) K14(2.5,1.5) K16(4.5,1.5) K17(5.5,1.5) K18(6.5,1.5) K19(7.5,1.5) K20(8.5,1.5) K21(9.5,1.5) K22(10.5,1.5) L1(-10.5,0.5) L2(-9.5,0.5) L3(-8.5,0.5) L4(-7.5,0.5) L5(-6.5,0.5) L6(-5.5,0.5) L7(-4.5,0.5) L9(-2.5,0.5) L10(-1.5,0.5) L11(-0.5,0.5) L12(0.5,0.5) L13(1.5,0.5) L14(2.5,0.5) L16(4.5,0.5) L17(5.5,0.5) L18(6.5,0.5) L19(7.5,0.5) L20(8.5,0.5) L21(9.5,0.5) L22(10.5,0.5) M1(-10.5,-0.5) M2(-9.5,-0.5) M3(-8.5,-0.5) M4(-7.5,-0.5) M5(-6.5,-0.5) M6(-5.5,-0.5) M7(-4.5,-0.5) M9(-2.5,-0.5) M10(-1.5,-0.5) M11(-0.5,-0.5) M12(0.5,-0.5) M13(1.5,-0.5) M14(2.5,-0.5) M16(4.5,-0.5) M17(5.5,-0.5) M18(6.5,-0.5) M19(7.5,-0.5) M20(8.5,-0.5) M21(9.5,-0.5) M22(10.5,-0.5) N1(-10.5,-1.5) N2(-9.5,-1.5) N3(-8.5,-1.5) N4(-7.5,-1.5) N5(-6.5,-1.5) N6(-5.5,-1.5) N7(-4.5,-1.5) N9(-2.5,-1.5) N10(-1.5,-1.5) N11(-0.5,-1.5) N12(0.5,-1.5) N13(1.5,-1.5) N14(2.5,-1.5) N16(4.5,-1.5) N17(5.5,-1.5) N18(6.5,-1.5) N19(7.5,-1.5) N20(8.5,-1.5) N21(9.5,-1.5) N22(10.5,-1.5) P1(-10.5,-2.5) P2(-9.5,-2.5) P3(-8.5,-2.5) P4(-7.5,-2.5) P5(-6.5,-2.5) P6(-5.5,-2.5) P7(-4.5,-2.5) P9(-2.5,-2.5) P10(-1.5,-2.5) P11(-0.5,-2.5) P12(0.5,-2.5) P13(1.5,-2.5) P14(2.5,-2.5) P16(4.5,-2.5) P17(5.5,-2.5) P18(6.5,-2.5) P19(7.5,-2.5) P20(8.5,-2.5) P21(9.5,-2.5) P22(10.5,-2.5) R1(-10.5,-3.5) R2(-9.5,-3.5) R3(-8.5,-3.5) R4(-7.5,-3.5) R5(-6.5,-3.5) R6(-5.5,-3.5) R7(-4.5,-3.5) R16(4.5,-3.5) R17(5.5,-3.5) R18(6.5,-3.5) R19(7.5,-3.5) R20(8.5,-3.5) R21(9.5,-3.5) R22(10.5,-3.5) T1(-10.5,-4.5) T2(-9.5,-4.5) T3(-8.5,-4.5) T4(-7.5,-4.5) T5(-6.5,-4.5) T6(-5.5,-4.5) T7(-4.5,-4.5) T8(-3.5,-4.5) T9(-2.5,-4.5) T10(-1.5,-4.5) T11(-0.5,-4.5) T12(0.5,-4.5) T13(1.5,-4.5) T14(2.5,-4.5) T15(3.5,-4.5) T16(4.5,-4.5) T17(5.5,-4.5) T18(6.5,-4.5) T19(7.5,-4.5) T20(8.5,-4.5) T21(9.5,-4.5) T22(10.5,-4.5) U1(-10.5,-5.5) U2(-9.5,-5.5) U3(-8.5,-5.5) U4(-7.5,-5.5) U5(-6.5,-5.5) U6(-5.5,-5.5) U7(-4.5,-5.5) U8(-3.5,-5.5) U9(-2.5,-5.5) U10(-1.5,-5.5) U11(-0.5,-5.5) U12(0.5,-5.5) U13(1.5,-5.5) U14(2.5,-5.5) U15(3.5,-5.5) U16(4.5,-5.5) U17(5.5,-5.5) U18(6.5,-5.5) U19(7.5,-5.5) U20(8.5,-5.5) U21(9.5,-5.5) U22(10.5,-5.5) V1(-10.5,-6.5) V2(-9.5,-6.5) V3(-8.5,-6.5) V4(-7.5,-6.5) V5(-6.5,-6.5) V6(-5.5,-6.5) V7(-4.5,-6.5) V8(-3.5,-6.5) V9(-2.5,-6.5) V10(-1.5,-6.5) V11(-0.5,-6.5) V12(0.5,-6.5) V13(1.5,-6.5) V14(2.5,-6.5) V15(3.5,-6.5) V16(4.5,-6.5) V17(5.5,-6.5) V18(6.5,-6.5) V19(7.5,-6.5) V20(8.5,-6.5) V21(9.5,-6.5) V22(10.5,-6.5) W1(-10.5,-7.5) W2(-9.5,-7.5) W3(-8.5,-7.5) W4(-7.5,-7.5) W5(-6.5,-7.5) W6(-5.5,-7.5) W7(-4.5,-7.5) W8(-3.5,-7.5) W9(-2.5,-7.5) W10(-1.5,-7.5) W11(-0.5,-7.5) W12(0.5,-7.5) W13(1.5,-7.5) W14(2.5,-7.5) W15(3.5,-7.5) W16(4.5,-7.5) W17(5.5,-7.5) W18(6.5,-7.5) W19(7.5,-7.5) W20(8.5,-7.5) W21(9.5,-7.5) W22(10.5,-7.5) Y1(-10.5,-8.5) Y2(-9.5,-8.5) Y3(-8.5,-8.5) Y4(-7.5,-8.5) Y5(-6.5,-8.5) Y6(-5.5,-8.5) Y7(-4.5,-8.5) Y8(-3.5,-8.5) Y9(-2.5,-8.5) Y10(-1.5,-8.5) Y11(-0.5,-8.5) Y12(0.5,-8.5) Y13(1.5,-8.5) Y14(2.5,-8.5) Y15(3.5,-8.5) Y16(4.5,-8.5) Y17(5.5,-8.5) Y18(6.5,-8.5) Y19(7.5,-8.5) Y20(8.5,-8.5) Y21(9.5,-8.5) Y22(10.5,-8.5)
Top Overlay:
  circle w0.25: c-12.15,10.5 r0.125
  lines w0.2: 10.5,-11.5 11.5,-10.5 11.5,10.5 ; 10.5,-11.5 10.5,-11.5 ; 10.5,-11.5 -10.5,-11.5 -11.5,-10.5 -11.5,11.5 10.5,11.5 11.5,10.5 ; 11.5,10.5 11.5,10.5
